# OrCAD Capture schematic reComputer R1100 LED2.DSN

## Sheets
1 02 LED: size A3; rev: v1.0
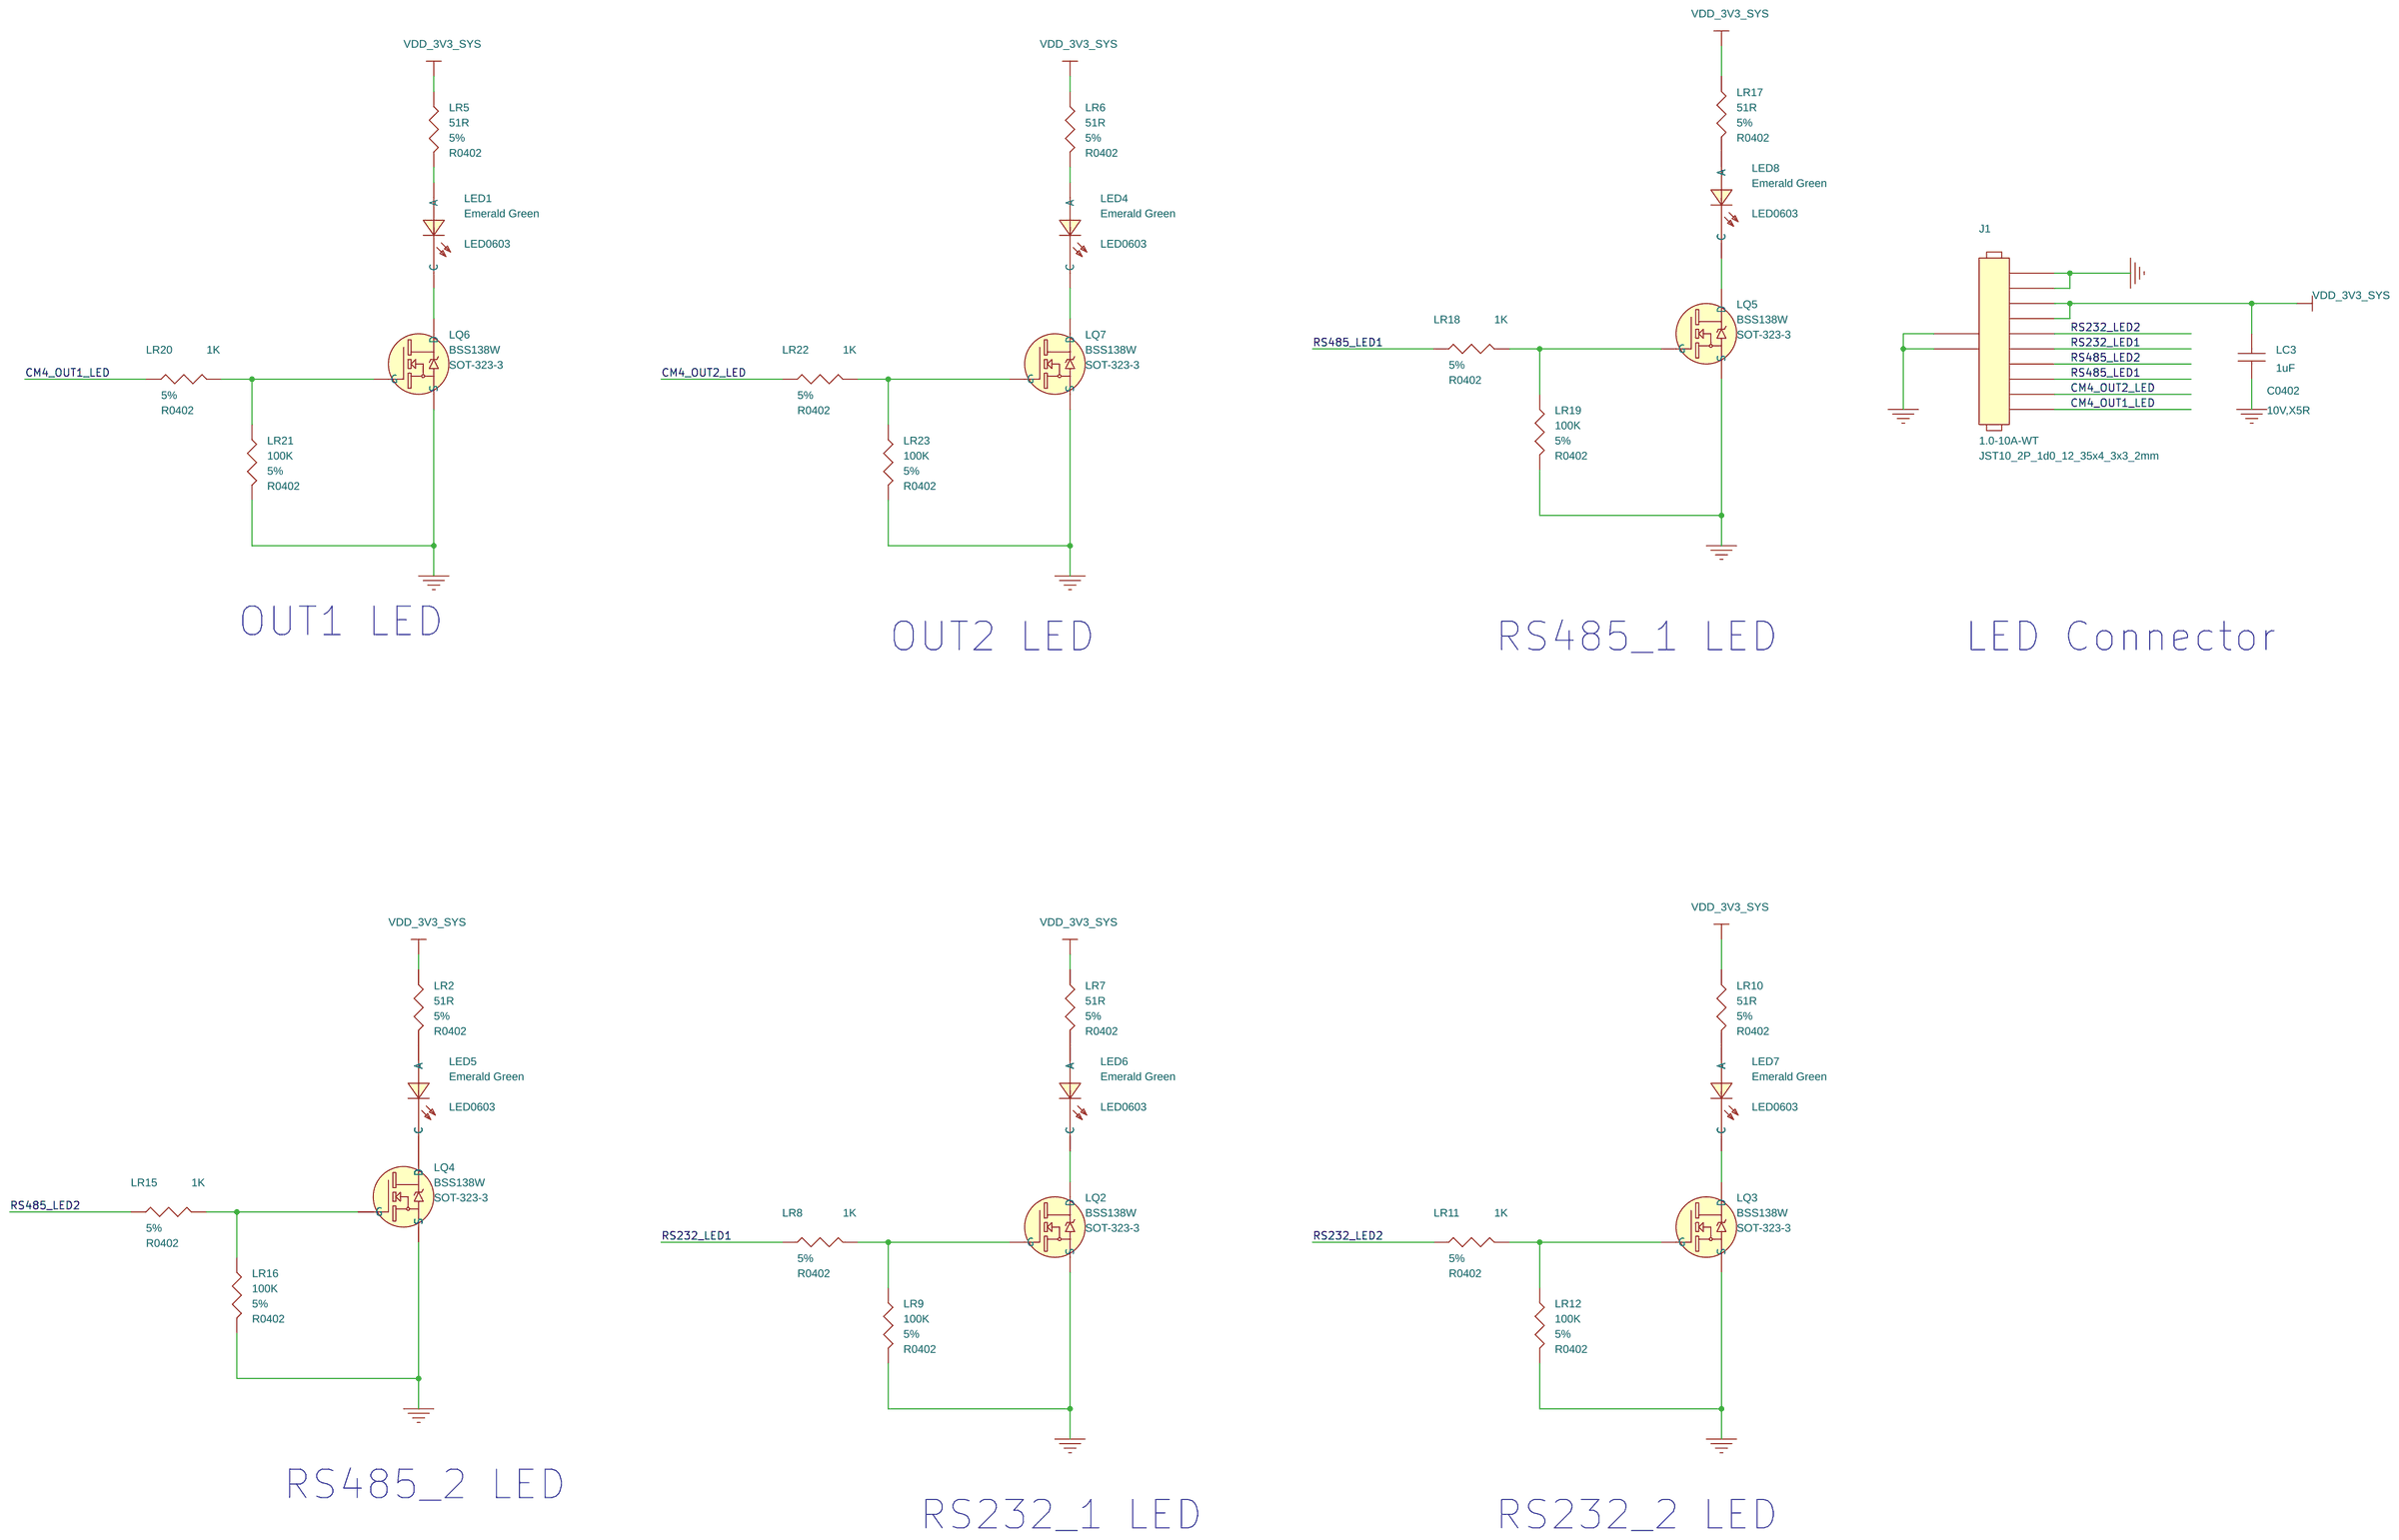
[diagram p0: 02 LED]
2 01 Title / Revision History
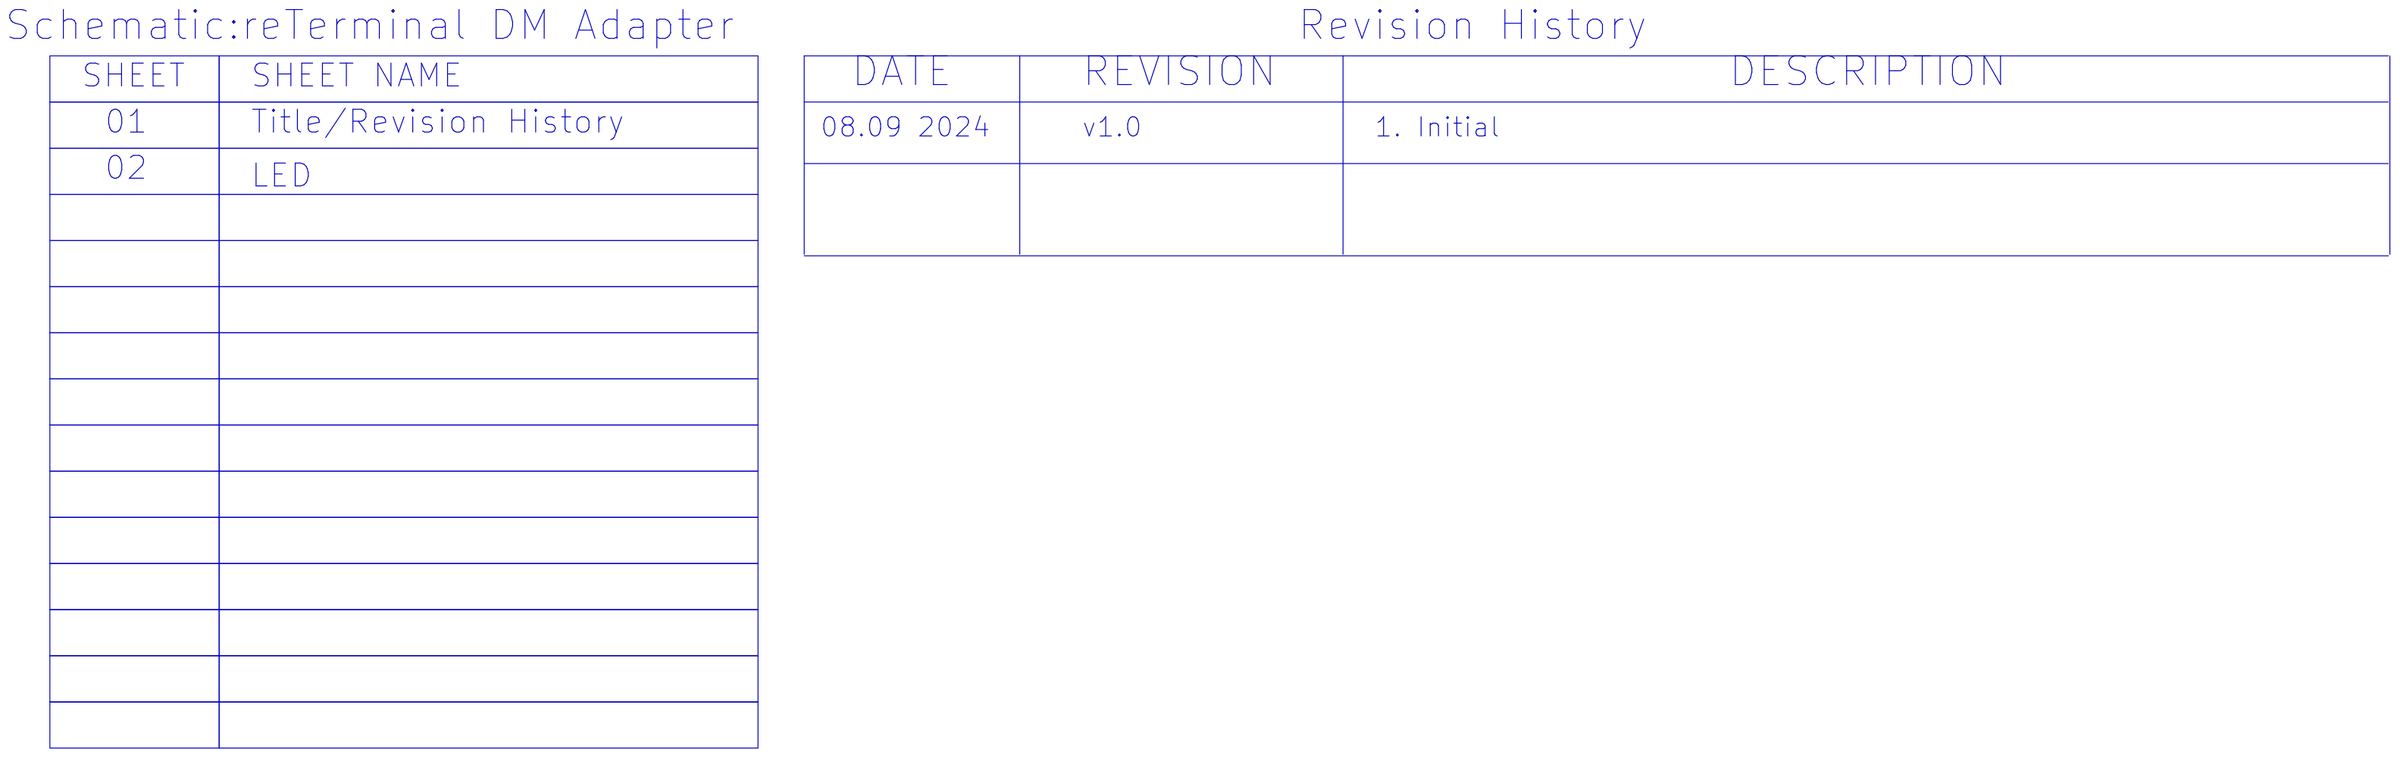
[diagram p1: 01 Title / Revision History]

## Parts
J1  1.0-10A-WT  [JST10_2P_1d0_12_35x4_3x3_2mm]
LC3  1uF  [C0402]
LED1  Emerald Green  [LED0603]
LED4  Emerald Green  [LED0603]
LED5  Emerald Green  [LED0603]
LED6  Emerald Green  [LED0603]
LED7  Emerald Green  [LED0603]
LED8  Emerald Green  [LED0603]
LQ2  BSS138W  [SOT-323-3]
LQ3  BSS138W  [SOT-323-3]
LQ4  BSS138W  [SOT-323-3]
LQ5  BSS138W  [SOT-323-3]
LQ6  BSS138W  [SOT-323-3]
LQ7  BSS138W  [SOT-323-3]
LR2  51R  [R0402]
LR5  51R  [R0402]
LR6  51R  [R0402]
LR7  51R  [R0402]
LR8  1K  [R0402]
LR9  100K  [R0402]
LR10  51R  [R0402]
LR11  1K  [R0402]
LR12  100K  [R0402]
LR15  1K  [R0402]
LR16  100K  [R0402]
LR17  51R  [R0402]
LR18  1K  [R0402]
LR19  100K  [R0402]
LR20  1K  [R0402]
LR21  100K  [R0402]
LR22  1K  [R0402]
LR23  100K  [R0402]

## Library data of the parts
J1 = JST_10+2P: SMD Male 1.0mm; 10P+2P-1.00mm; Manufacturer: 思拓展; PN: 320112081; Package Size: 1.0-10P; Status: reComputer R1002; Temperature: -25°C to 70°C
LC3 = CC: SMD CAP Ceramic 1uF-10V-10%-X5R;0402; Manufacturer: YAGEO; Manufacturer Part Number: CC0402KRX5R6BB105; PN: 302010040; Part Type: Ceramic; Rating: 10V,X5R; Status: BeagleBone Carrier Board; Temperature: -55°C to 85°C
LED1 LED4-LED8 = Single_LED: SMD LED Clear-Green;LED-0603; Manufacturer: Everlight; Manufacturer Part Number: 19-217/GHC-YR1S2/6T; PN: 304092047; Package Size: 0603; Status: ReComputer R1000; Temperature: -40°C to 85°C
LQ2-LQ7 = NMOS_123: SMD MOSFET N-CH 50V-200mA;SOT-323-3; Manufacturer: Diodes; Manufacturer Part Number: BSS138W-7-F; PN: 305030000; Part Type: NMOS; Rating: 50V 200mA; Status: BeagleBone Carrier Board; Temperature: -55°C to 150°C
LR2 LR5-LR7 LR10 LR17 = R: SMD RES 51R-5%-1/16W;0402; Manufacturer: YAGEO; Manufacturer Part Number: RC0402JR-0751RL; PN: 301010080; Package Size: 0402; Rating: 5%; Temperature: -55°C to 155°C
LR8 LR11 LR15 LR18 LR20 LR22 = R: SMD RES 1K-5%-1/16W;0402; Manufacturer: YAGEO; Manufacturer Part Number: RC0402JR-071KL; PN: 301010006; Part Type: RES; Rating: 5%; Status: BeagleBone Carrier Board; Temperature: -55°C to 155°C
LR9 LR12 LR16 LR19 LR21 LR23 = R: SMD RES 100K-5%-1/16W;0402; Manufacturer: YAGEO; Manufacturer Part Number: RC0402JR-07100KL; PN: 301010033; Part Type: RES; Rating: 5%; Status: BeagleBone Carrier Board; Temperature: -55°C to 155°C

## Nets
GND: J1.1 J1.2 J1.S1 J1.S2 LC3.1 LQ2.2(S) LQ3.2(S) LQ4.2(S) LQ5.2(S) LQ6.2(S) LQ7.2(S) LR9.2 LR12.2 LR16.2 LR19.2 LR21.2 LR23.2
VDD_3V3_SYS: J1.3 J1.4 LC3.2 LR2.1 LR5.1 LR6.1 LR7.1 LR10.1 LR17.1
CM4_OUT1_LED: J1.10 LR20.1
CM4_OUT2_LED: J1.9 LR22.1
RS232_LED1: J1.6 LR8.1
RS232_LED2: J1.5 LR11.1
RS485_LED1: J1.8 LR18.1
RS485_LED2: J1.7 LR15.1
N19189: LED4.1(A) LR6.2
N20057: LED6.2(C) LQ2.3(D)
N20113: LQ2.1(G) LR8.2 LR9.1
N20605: LED7.2(C) LQ3.3(D)
N20661: LQ3.1(G) LR11.2 LR12.1
N33927: LED5.1(A) LR2.2
N33969: LED6.1(A) LR7.2
N34011: LED7.1(A) LR10.2
N36522: LQ4.1(G) LR15.2 LR16.1
N36614: LED5.2(C) LQ4.3(D)
N36850: LED8.2(C) LQ5.3(D)
N36906: LQ5.1(G) LR18.2 LR19.1
N37720: LED1.1(A) LR5.2
N38126: LED8.1(A) LR17.2
N48529: LQ6.1(G) LR20.2 LR21.1
N48764: LQ7.1(G) LR22.2 LR23.1
N49368: LED1.2(C) LQ6.3(D)
N49372: LED4.2(C) LQ7.3(D)

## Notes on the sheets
sheet 1
- OUT1 LED
- OUT2 LED
- RS485_1 LED
- LED Connector
- RS485_2 LED
- RS232_1 LED
- RS232_2 LED
sheet 2
- Schematic:reTerminal DM Adapter
- Revision History
- SHEET
- SHEET NAME
- DATE
- REVISION
- DESCRIPTION
- 01
- Title/Revision History
- 08.09 2024
- v1.0
- 1. Initial
- 02
- LED
